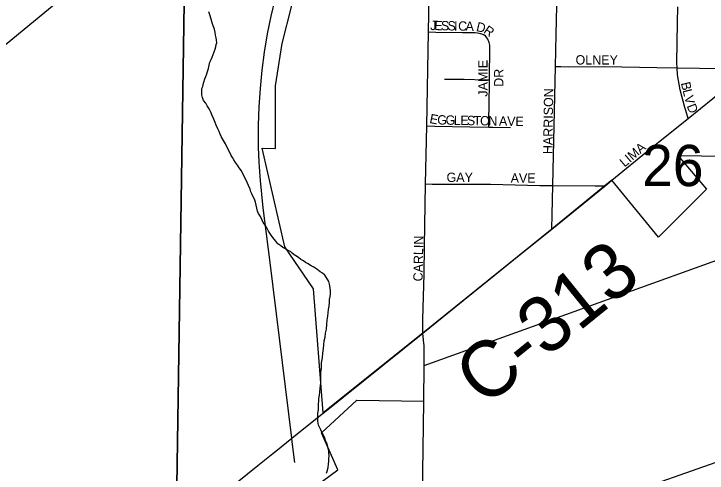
# Model space of a CAD drawing. Extents: x 1587405 to 1714697, y 1028970 to 1155083.
# Drawn here: x 1639431 to 1643143, y 1098788 to 1101248 of the extents above; entities that cross this region are included whole.
import ezdxf

# ---------------------------------------------------------------- set-up
doc = ezdxf.new("R2010")
doc.units = 0
for name, color, linetype in [('GM_X_City_Street', 7, 'Continuous'), ('GM_X_City_Street_Text', 7, 'Continuous'), ('GM_X_Corporation', 7, 'Continuous'), ('GM_X_County_Road', 7, 'Continuous'), ('GM_X_County_Road_Text', 7, 'Continuous'), ('GM_X_Interstate_Route', 7, 'Continuous'), ('GM_X_Minor_River', 7, 'Continuous'), ('GM_X_Rail_Line', 7, 'Continuous'), ('GM_X_Section', 7, 'Continuous'), ('GM_X_Section_Text', 7, 'Continuous'), ('GM_X_Township_Road', 7, 'Continuous')]:
    doc.layers.add(name, color=color, linetype=linetype)

msp = doc.modelspace()

# ---------------------------------------------------------------- linework, layer by layer
at = {"layer": 'GM_X_City_Street'}
for points in [[(1641651.6, 1101151.6), (1641660.6, 1101629.6)], [(1642330.7, 1100967), (1642334.1, 1101138.7), (1642337.4, 1101291.4)], [(1642982.1, 1100958.7), (1642979.8, 1100987.5), (1642984.7, 1101200.8), (1642985.9, 1101285.4)], [(1641641.5, 1100648.8), (1641651.6, 1101151.6)], [(1641651.6, 1101151.6), (1641691, 1101150.9), (1641832.3, 1101149.2), (1641888, 1101148.6), (1641901.2, 1101147.9), (1641913.1, 1101147.1), (1641922.7, 1101145.4), (1641930.1, 1101143.4), (1641939.5, 1101140.5), (1641945.4, 1101138.1), (1641950.7, 1101134.9)], [(1641977, 1100894.6), (1641977.6, 1100935.6), (1641979.6, 1101034.1), (1641979.4, 1101070.6), (1641978.6, 1101081.5), (1641977.6, 1101088), (1641975.8, 1101094.8), (1641973.8, 1101100.8), (1641971.3, 1101107), (1641968.2, 1101113.6), (1641963.8, 1101120.9), (1641960.2, 1101126), (1641956.8, 1101130.1), (1641950.7, 1101134.9)], [(1642316.5, 1100329.2), (1642324.3, 1100648.2), (1642330.7, 1100967)], [(1642330.7, 1100967), (1642359.1, 1100965.8), (1642400.3, 1100964.1), (1642593.1, 1100965.7), (1642873.9, 1100960.4), (1642982.1, 1100958.7)], [(1643041.2, 1100688.4), (1643028.4, 1100730.4), (1643023.7, 1100746.1), (1642998.7, 1100841.3), (1642985, 1100922.1), (1642982.1, 1100958.7)], [(1642982.1, 1100958.7), (1643221.3, 1100955), (1643335, 1100957.5), (1643375.8, 1100958.4)], [(1643041.2, 1100688.4), (1643240.3, 1100848.7), (1643375.8, 1100958.4)], [(1641736.6, 1100899.2), (1641775.9, 1100899.2), (1641841.4, 1100898.2), (1641954.2, 1100895.2), (1641977, 1100894.6)], [(1641973.7, 1100641.7), (1641974.3, 1100676.3), (1641976, 1100765.1), (1641976.8, 1100883.2), (1641977, 1100894.6)], [(1642838.3, 1100524.7), (1642882.5, 1100560.7), (1643041.2, 1100688.4)], [(1641635.3, 1100337.1), (1641641.5, 1100648.8)], [(1641641.5, 1100648.8), (1641684.5, 1100647.4), (1641872, 1100643.3), (1641973.7, 1100641.7)], [(1641973.7, 1100641.7), (1641996.3, 1100641.3), (1642090.1, 1100639.8)], [(1642632.1, 1100356.7), (1642838.3, 1100524.7)], [(1641619.8, 1099537.2), (1641621.5, 1099610.6), (1641627.2, 1099856.2), (1641628.8, 1100003.6), (1641635.3, 1100337.1)], [(1641635.3, 1100337.1), (1641670.7, 1100336.9), (1641983.5, 1100335.6), (1642246.6, 1100329.7), (1642316.5, 1100329.2)], [(1642310.5, 1100094.7), (1642312.5, 1100172.9), (1642316.5, 1100329.2)], [(1642316.5, 1100329.2), (1642542.7, 1100327.7), (1642596.1, 1100327.3)], [(1641615.3, 1098458.3), (1641620.3, 1098793.3), (1641626.7, 1099170.6), (1641626.7, 1099173.3)]]:
    msp.add_lwpolyline(points, dxfattribs=at)
at = {"layer": 'GM_X_Corporation'}
for points in [[(1643984.2, 1100474.1), (1642987.2, 1100488.7), (1643139.1, 1100310.1), (1642883.2, 1100052.9), (1642632.1, 1100356.7), (1642596, 1100327.3), (1642310.5, 1100094.7), (1641619.8, 1099537.2), (1641087.3, 1099110.3), (1641034.5, 1099775.5), (1640881.9, 1100000.7), (1640761.1, 1100528.1), (1640832.6, 1100526.4), (1640832.6, 1100608.8), (1640832.4, 1100863.7), (1640867.1, 1101089.7), (1640919.1, 1101292.5), (1640976.9, 1101530.1), (1641029, 1101640.2), (1641129.7, 1101855.1), (1641031, 1101864.1), (1640924, 1101866.8), (1640358.2, 1101881.3), (1640363.2, 1103157.7)], [(1641042.7, 1098714.4), (1641166.1, 1098805), (1641078.5, 1099004.6), (1641267.1, 1099179.2), (1641626.7, 1099173.3), (1641628.3, 1099364.6), (1644286, 1100321.1)], [(1646111.4, 1097716.2), (1646119.4, 1099376.9), (1645601.6, 1099394.7), (1645607.3, 1099735.8), (1645421.4, 1099742.2), (1645213.7, 1099585.6), (1645208.7, 1099288.5), (1645003.9, 1099507.9), (1644279.3, 1099229.4), (1641612.5, 1098290)]]:
    msp.add_lwpolyline(points, dxfattribs=at)
at = {"layer": 'GM_X_County_Road'}
for points in [[(1642596.1, 1100327.3), (1642632.1, 1100356.7)], [(1642310.5, 1100094.7), (1642596.1, 1100327.3)], [(1641619.8, 1099537.2), (1641837.3, 1099713.7), (1642003.3, 1099847.5), (1642143.6, 1099961.1), (1642284.6, 1100073.7), (1642310.5, 1100094.7)], [(1641084.5, 1099108), (1641619.8, 1099537.2)], [(1640833.4, 1098905.9), (1640919.4, 1098975), (1641081.1, 1099105.3), (1641084.5, 1099108)], [(1637591, 1096302.7), (1637692.8, 1096383.2), (1637832.5, 1096497.4), (1638152.4, 1096754), (1638293.2, 1096867), (1638601, 1097112.5), (1638933, 1097380.4), (1639137.6, 1097544.7), (1639341.4, 1097710.2), (1639534.7, 1097862.4), (1640097, 1098315.1), (1640352.2, 1098521.3), (1640506.8, 1098642.9), (1640736.4, 1098828.5), (1640818.4, 1098893.8), (1640833.4, 1098905.9)]]:
    msp.add_lwpolyline(points, dxfattribs=at)
at = {"layer": 'GM_X_Interstate_Route'}
for points in [[(1640741.3, 1100535), (1640740.7, 1100553), (1640740.9, 1100651.7), (1640744.7, 1100750.3), (1640751.7, 1100848.7), (1640760.2, 1100947.5), (1640772.3, 1101042.9), (1640789.2, 1101142.3), (1640808.8, 1101237), (1640832.4, 1101335.1), (1640859.4, 1101429.1), (1640894.5, 1101538), (1640928.3, 1101631.4), (1640966.1, 1101724.7), (1641004.6, 1101811.3), (1641026.2, 1101854.6)], [(1640746, 1100429.4), (1640744.2, 1100454.5), (1640741.3, 1100535)], [(1640921.8, 1098955.3), (1640919.4, 1098975), (1640802.6, 1099915.7), (1640766.4, 1100209), (1640751.2, 1100356.1), (1640746, 1100429.4)], [(1640935.5, 1098845.2), (1640921.8, 1098955.3)]]:
    msp.add_lwpolyline(points, dxfattribs=at)
at = {"layer": 'GM_X_Minor_River'}
for points in [[(1640543, 1100587.8), (1640535.3, 1100604.1), (1640529.6, 1100618.2), (1640523.9, 1100632.4), (1640514.2, 1100652.6), (1640508.5, 1100666.8), (1640500.9, 1100685), (1640493.2, 1100703.2), (1640485.5, 1100721.4), (1640475.9, 1100739.7), (1640466.2, 1100755.9), (1640458.4, 1100770.1), (1640446.7, 1100784.4), (1640441, 1100800.6), (1640437.3, 1100814.7), (1640437.6, 1100830.7), (1640438, 1100848.8), (1640442.2, 1100858.7), (1640444.4, 1100870.7), (1640448.7, 1100882.6), (1640453.1, 1100900.6), (1640459.3, 1100912.5), (1640463.6, 1100926.5), (1640467.9, 1100940.4), (1640472.2, 1100956.4), (1640476.6, 1100974.4), (1640481, 1100990.3), (1640487.3, 1101004.2), (1640493.5, 1101016.1), (1640508.5, 1101060), (1640512.7, 1101071.9), (1640515, 1101083.9), (1640517.2, 1101093.9), (1640515.4, 1101108), (1640513.7, 1101120), (1640510, 1101134.2), (1640508.2, 1101148.2), (1640504.6, 1101166.4), (1640498.9, 1101184.5), (1640493.2, 1101200.7), (1640487.6, 1101220.9), (1640480.1, 1101243.1), (1640474.4, 1101259.3)], [(1641107.8, 1098945.4), (1641102, 1098957.6), (1641096.3, 1098975.7), (1641075.2, 1099020.3), (1641069.4, 1099030.4), (1641061.6, 1099044.6), (1641058, 1099066.8), (1641058.4, 1099084.8), (1641058.9, 1099108.9), (1641061.3, 1099126.9), (1641061.6, 1099142.9), (1641061.9, 1099159), (1641064.2, 1099173), (1641064.5, 1099187), (1641066.9, 1099205), (1641069.2, 1099223), (1641071.6, 1099241), (1641071.9, 1099257.1), (1641074.2, 1099271.1), (1641074.8, 1099301.2), (1641075.4, 1099327.2), (1641077.9, 1099351.2), (1641078.4, 1099379.3), (1641083, 1099405.3), (1641085.5, 1099431.3), (1641088, 1099455.3), (1641090.4, 1099475.4), (1641092.9, 1099497.4), (1641097.3, 1099517.3), (1641099.7, 1099537.4), (1641104.1, 1099559.3), (1641106.7, 1099585.4), (1641109.1, 1099607.4), (1641111.6, 1099629.4), (1641114, 1099647.4), (1641116.3, 1099665.4), (1641118.7, 1099683.4), (1641121.1, 1099701.4), (1641121.4, 1099717.5), (1641123.7, 1099733.5), (1641126, 1099747.5), (1641126.4, 1099765.5), (1641124.7, 1099781.6), (1641121.1, 1099799.7), (1641117.3, 1099813.8), (1641103.8, 1099838.2), (1641096, 1099848.4), (1641084.1, 1099858.6), (1641070.2, 1099866.9), (1641052.5, 1099881.3), (1641042.6, 1099887.6), (1641032.7, 1099893.8), (1641022.7, 1099898), (1641002.9, 1099910.4), (1640993, 1099916.7), (1640981.1, 1099924.9), (1640967.2, 1099933.2), (1640955.4, 1099943.5), (1640941.5, 1099951.8), (1640931.6, 1099958), (1640921.7, 1099966.3), (1640911.9, 1099974.5), (1640898, 1099980.8), (1640886.1, 1099989.1), (1640870.2, 1099997.4), (1640860.3, 1100005.6), (1640844.5, 1100016), (1640832.8, 1100030.3), (1640817.1, 1100050.6), (1640809.3, 1100062.8), (1640801.5, 1100073), (1640793.7, 1100085.2), (1640786, 1100101.4), (1640776.3, 1100115.7), (1640766.5, 1100129.9), (1640758.8, 1100146.1), (1640751.1, 1100162.3), (1640741.4, 1100178.6), (1640735.7, 1100190.7), (1640732, 1100206.8), (1640728.3, 1100223), (1640724.6, 1100239.1), (1640718.9, 1100255.3), (1640713.1, 1100267.4), (1640705.4, 1100283.6), (1640699.7, 1100295.8), (1640695.9, 1100309.9), (1640671, 1100364.6), (1640661.3, 1100384.8), (1640649.7, 1100407.1), (1640638, 1100423.4), (1640628.3, 1100437.6), (1640618.5, 1100451.9), (1640608.8, 1100466.1), (1640601, 1100478.3), (1640595.2, 1100490.5), (1640589.5, 1100502.6), (1640581.7, 1100514.8), (1640564.4, 1100551.3), (1640552.7, 1100569.6), (1640543, 1100587.8)], [(1641104.6, 1098787), (1641108.8, 1098798.9), (1641113.2, 1098818.9), (1641115.6, 1098836.9), (1641117.9, 1098852.9), (1641118.1, 1098862.9), (1641118.5, 1098883), (1641116.8, 1098895.1), (1641117, 1098905.1), (1641113.3, 1098921.2), (1641111.5, 1098931.3), (1641107.8, 1098945.4)]]:
    msp.add_lwpolyline(points, dxfattribs=at)
at = {"layer": 'GM_X_Rail_Line'}
msp.add_lwpolyline([(1629314.4, 1092809.9), (1631806.5, 1094856.6), (1635602.9, 1097976.6), (1637660.3, 1099664.7), (1641894.6, 1103150.5)], dxfattribs=at)
at = {"layer": 'GM_X_Section'}
for points in [[(1640371.5, 1103190.4), (1640291.9, 1097896.4), (1634954.2, 1097996.5), (1635067.7, 1103292.1)], [(1645653.7, 1103119), (1645545.8, 1097805.3), (1640291.9, 1097896.4), (1640371.5, 1103190.4)]]:
    msp.add_lwpolyline(points, close=True, dxfattribs=at)
at = {"layer": 'GM_X_Township_Road'}
for points in [[(1641628.3, 1099364.6), (1641628.4, 1099433.2), (1641627.5, 1099470.7), (1641624, 1099501), (1641619.8, 1099537.2)], [(1641626.7, 1099173.3), (1641628.3, 1099364.6)]]:
    msp.add_lwpolyline(points, dxfattribs=at)

# ---------------------------------------------------------------- texts
at = {"layer": 'GM_X_City_Street_Text'}
for s, rotation, p in [('J', 358.8193, (1641659.7, 1101161.9)), ('E', 358.8253, (1641681.7, 1101161.5)), ('S', 358.798, (1641716.9, 1101160.7)), ('S', 358.8399, (1641752.1, 1101160)), ('I', 358.8193, (1641787.3, 1101159.3)), ('C', 358.8101, (1641809.3, 1101158.8)), ('A', 358.8329, (1641848.9, 1101158)), ('D', 346.7482, (1641903.4, 1101157.2)), ('R', 325.01, (1641941.6, 1101149.1)), ('OLNEY', 0, (1642438.4, 1100977.1)), ('JAMIE', 90, (1641967, 1100804.9)), ('DR', 90, (1642052.1, 1100857.7)), ('B', 283.6828, (1643001.9, 1100877.5)), ('HARRISON', 89.2062, (1642314.6, 1100496.7)), ('L', 283.6785, (1643011.3, 1100839)), ('V', 284.2738, (1643019.8, 1100804.3)), ('D', 291.5354, (1643032.7, 1100755.1)), ('E', 348.6954, (1641653.7, 1100664.3)), ('G', 358.0675, (1641697.1, 1100656.4)), ('G', 358.9569, (1641741.9, 1100654.8)), ('L', 358.9345, (1641785.9, 1100654)), ('E', 358.9644, (1641821.1, 1100653.4)), ('S', 358.9345, (1641856.3, 1100652.7)), ('T', 358.9345, (1641891.5, 1100652.1)), ('O', 358.9569, (1641926.7, 1100651.4)), ('N', 358.929, (1641970.7, 1100650.6)), ('A', 358.9508, (1642027.9, 1100649.6)), ('V', 358.929, (1642071.9, 1100648.8)), ('E', 358.9532, (1642115.9, 1100647.9)), ('LIMA', 40.4282, (1642700.7, 1100424.9)), ('GAY', 0, (1641747.6, 1100347.9)), ('AVE', 0, (1642090.8, 1100343.5)), ('CARLIN', 88.9221, (1641619.4, 1099814.7))]:
    msp.add_text(s, height=50, rotation=rotation, dxfattribs=at).set_placement(p)
at = {"layer": 'GM_X_County_Road_Text'}
msp.add_text('C-313', height=300, rotation=38.963, dxfattribs=at).set_placement((1641951.7, 1099136.5))
at = {"layer": 'GM_X_Section_Text'}
msp.add_text('26', height=221, rotation=0, dxfattribs=at).set_placement((1642794.8, 1100325.6))

doc.saveas('drawing.dxf')
